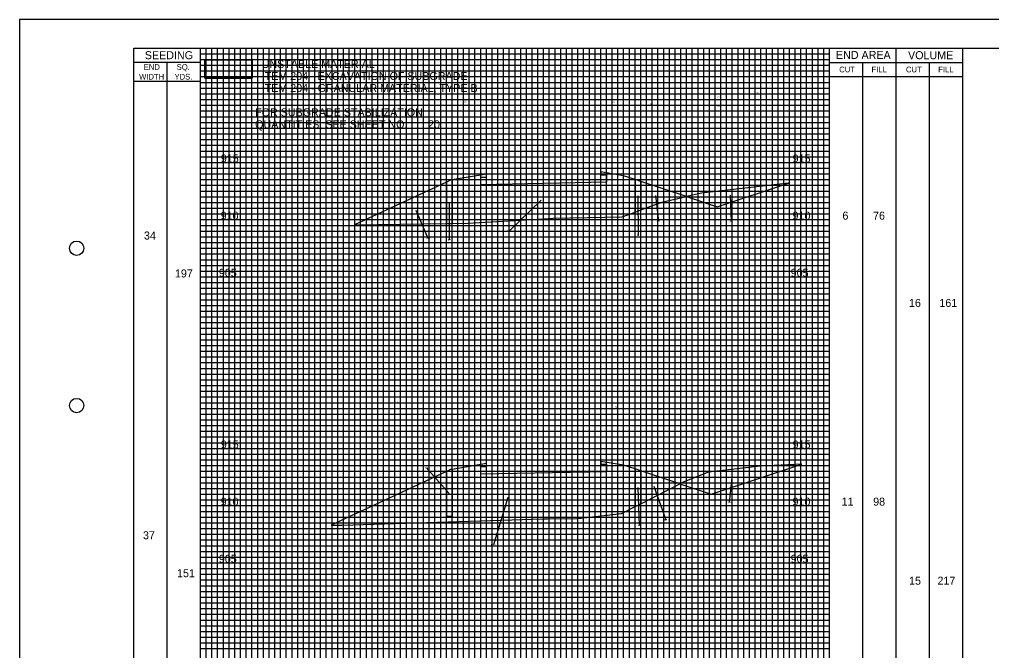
# Model space of a CAD drawing. Extents: x -73 to 160, y -2 to 1877.
# Drawn here: x -10 to 75, y 627.3 to 682.5 of the extents above; entities that cross this region are included whole.
import ezdxf

# ---------------------------------------------------------------- set-up
doc = ezdxf.new("R2010")
doc.units = 0
for name, color, linetype in [('DR_P_Flood_Boundary', 7, 'Continuous'), ('GK_Cells', 7, 'Continuous'), ('PV_P_EOP', 7, 'Continuous'), ('RD_X_Fence', 7, 'Continuous'), ('TX_X_5', 7, 'Continuous'), ('UT_P_Water_Cells', 7, 'Continuous'), ('XS_P_Pavt_Surface', 7, 'Continuous'), ('XS_P_Special_Benching', 7, 'Continuous'), ('XS_X_Ground_Line', 7, 'Continuous')]:
    doc.layers.add(name, color=color, linetype=linetype)

msp = doc.modelspace()

# ---------------------------------------------------------------- linework, layer by layer
at = {"layer": 'DR_P_Flood_Boundary'}
for p, q in [((10.832, 575), (10.832, 680)), ((15.832, 575), (15.832, 680)), ((20.832, 575), (20.832, 680)), ((25.832, 575), (25.832, 680)), ((30.832, 575), (30.832, 680)), ((35.832, 575), (35.832, 680)), ((40.832, 575), (40.832, 680)), ((45.832, 575), (45.832, 680)), ((50.832, 575), (50.832, 680)), ((55.832, 575), (55.832, 680)), ((5.832, 675), (60.832, 675)), ((5.832, 670), (60.832, 670)), ((5.832, 665), (60.832, 665)), ((5.832, 660), (60.832, 660)), ((5.832, 655), (60.832, 655)), ((5.832, 650), (60.832, 650)), ((5.832, 645), (60.832, 645)), ((5.832, 640), (60.832, 640)), ((5.832, 635), (60.832, 635)), ((5.832, 630), (60.832, 630))]:
    msp.add_line(p, q, dxfattribs=at)
at = {"layer": 'GK_Cells'}
msp.add_lwpolyline([(0, 680), (157.5, 680), (157.5, 575), (0, 575)], close=True, dxfattribs=at)
for centre in [(-5, 662.5), (-5, 648.75)]:
    msp.add_circle(centre, 0.625, dxfattribs=at)
at = {"layer": 'PV_P_EOP'}
msp.add_lwpolyline([(6.212, 678.971), (10.353, 678.971), (10.353, 677.356), (6.212, 677.356)], close=True, dxfattribs=at)
msp.add_lwpolyline([(6.212, 677.356), (10.353, 677.356), (10.353, 678.971), (6.212, 678.971), (6.212, 677.356)], dxfattribs=at)
at = {"layer": 'RD_X_Fence'}
for p, q in [((30.832, 668.97), (27.832, 668.47)), ((42.832, 668.837), (40.832, 669.17)), ((27.332, 668.278), (19.296, 664.541)), ((27.698, 668.448), (27.332, 668.278)), ((27.332, 664.661), (27.332, 668.278)), ((27.332, 668.278), (27.332, 664.661)), ((27.832, 668.47), (27.698, 668.448)), ((27.832, 664.668), (27.832, 668.47)), ((27.832, 668.47), (27.832, 664.668)), ((30.332, 668.71), (30.832, 668.72)), ((30.332, 668.043), (30.332, 668.71)), ((41.332, 668.263), (30.332, 668.043)), ((40.832, 668.92), (41.332, 668.93)), ((41.332, 668.93), (41.332, 668.263)), ((43.832, 668.503), (42.832, 668.837)), ((43.832, 665.663), (43.832, 668.503)), ((44.332, 668.337), (43.832, 668.503)), ((43.832, 668.503), (43.832, 665.663)), ((44.332, 665.848), (44.332, 668.337)), ((44.332, 668.337), (44.332, 665.848)), ((48.314, 667.009), (44.332, 668.337)), ((51.012, 666.11), (57.249, 668.189)), ((27.585, 666.527), (27.581, 663.246)), ((35.63, 666.701), (32.819, 663.985)), ((44.077, 667.088), (44.105, 663.627)), ((45.623, 667.101), (45.867, 664.866)), ((48.314, 667.009), (51.012, 666.11)), ((52.151, 667.139), (52.23, 664.836)), ((24.654, 665.826), (25.723, 663.389)), ((43.832, 665.663), (44.332, 665.848)), ((19.296, 664.541), (27.332, 664.661)), ((27.332, 664.661), (27.832, 664.668)), ((30.832, 643.67), (27.832, 643.17)), ((42.832, 643.537), (40.832, 643.87)), ((40.832, 643.62), (41.332, 643.63)), ((41.332, 643.63), (41.332, 642.963)), ((43.832, 643.203), (42.832, 643.537)), ((50.472, 640.99), (58.419, 643.639)), ((27.332, 642.978), (17.247, 638.288)), ((27.585, 641.068), (25.603, 643.3)), ((27.698, 643.148), (27.332, 642.978)), ((27.332, 639.047), (27.332, 642.978)), ((27.332, 642.978), (27.332, 639.047)), ((27.832, 643.17), (27.698, 643.148)), ((27.832, 643.17), (27.832, 639.047)), ((27.832, 639.047), (27.832, 643.17)), ((30.332, 643.41), (30.832, 643.42)), ((30.332, 642.743), (30.332, 643.41)), ((41.332, 642.963), (30.332, 642.743)), ((43.832, 639.918), (43.832, 643.203)), ((44.332, 643.037), (43.832, 643.203)), ((43.832, 643.203), (43.832, 639.918)), ((44.332, 640.171), (44.332, 643.037)), ((47.748, 641.898), (44.332, 643.037)), ((44.332, 643.037), (44.332, 640.171)), ((44.332, 640.171), (47.748, 641.898)), ((47.748, 641.898), (50.472, 640.99)), ((52.294, 642.431), (52.053, 640.31)), ((44.077, 641.582), (44.195, 638.249)), ((45.471, 641.702), (46.508, 638.756)), ((32.699, 640.717), (31.445, 636.582)), ((43.832, 639.918), (44.332, 640.171)), ((27.832, 639.047), (27.332, 639.047)), ((27.332, 639.047), (27.832, 639.047))]:
    msp.add_line(p, q, dxfattribs=at)
for points in [[(30.832, 668.72), (30.832, 668.866), (30.832, 668.97)], [(40.832, 669.17), (40.832, 669.066), (40.832, 668.92)], [(57.249, 668.189), (49.639, 667.308), (48.314, 667.009)], [(44.332, 665.848), (46.162, 666.524), (48.314, 667.009)], [(27.832, 664.668), (29.207, 664.688), (35.832, 665.072), (36.63, 665.118), (42.69, 665.241), (43.832, 665.663)], [(30.832, 643.42), (30.832, 643.566), (30.832, 643.67)], [(40.832, 643.87), (40.832, 643.766), (40.832, 643.62)], [(58.419, 643.639), (54.771, 643.464), (50.243, 642.938), (48.035, 642.043), (47.748, 641.898)], [(17.247, 638.288), (18.217, 638.303), (35.833, 638.835), (36.166, 638.845), (38.844, 638.879), (42.655, 639.322), (43.832, 639.918)]]:
    msp.add_lwpolyline(points, dxfattribs=at)
at = {"layer": 'TX_X_5'}
msp.add_lwpolyline([(-10, 572.5), (160, 572.5), (160, 682.5), (-10, 682.5)], close=True, dxfattribs=at)
at = {"layer": 'UT_P_Water_Cells'}
for p, q in [((6.332, 575), (6.332, 680)), ((6.832, 575), (6.832, 680)), ((7.332, 575), (7.332, 680)), ((7.832, 575), (7.832, 680)), ((8.332, 575), (8.332, 680)), ((8.832, 575), (8.832, 680)), ((9.332, 575), (9.332, 680)), ((9.832, 575), (9.832, 680)), ((10.332, 575), (10.332, 680)), ((11.332, 575), (11.332, 680)), ((11.832, 575), (11.832, 680)), ((12.332, 575), (12.332, 680)), ((12.832, 575), (12.832, 680)), ((13.332, 575), (13.332, 680)), ((13.832, 575), (13.832, 680)), ((14.332, 575), (14.332, 680)), ((14.832, 575), (14.832, 680)), ((15.332, 575), (15.332, 680)), ((16.332, 575), (16.332, 680)), ((16.832, 575), (16.832, 680)), ((17.332, 575), (17.332, 680)), ((17.832, 575), (17.832, 680)), ((18.332, 575), (18.332, 680)), ((18.832, 575), (18.832, 680)), ((19.332, 575), (19.332, 680)), ((19.832, 575), (19.832, 680)), ((20.332, 575), (20.332, 680)), ((21.332, 575), (21.332, 680)), ((21.832, 575), (21.832, 680)), ((22.332, 575), (22.332, 680)), ((22.832, 575), (22.832, 680)), ((23.332, 575), (23.332, 680)), ((23.832, 575), (23.832, 680)), ((24.332, 575), (24.332, 680)), ((24.832, 575), (24.832, 680)), ((25.332, 575), (25.332, 680)), ((26.332, 575), (26.332, 680)), ((26.832, 575), (26.832, 680)), ((27.332, 575), (27.332, 680)), ((27.832, 575), (27.832, 680)), ((28.332, 575), (28.332, 680)), ((28.832, 575), (28.832, 680)), ((29.332, 575), (29.332, 680)), ((29.832, 575), (29.832, 680)), ((30.332, 575), (30.332, 680)), ((31.332, 575), (31.332, 680)), ((31.832, 575), (31.832, 680)), ((32.332, 575), (32.332, 680)), ((32.832, 575), (32.832, 680)), ((33.332, 575), (33.332, 680)), ((33.832, 575), (33.832, 680)), ((34.332, 575), (34.332, 680)), ((34.832, 575), (34.832, 680)), ((35.332, 575), (35.332, 680)), ((36.332, 575), (36.332, 680)), ((36.832, 575), (36.832, 680)), ((37.332, 575), (37.332, 680)), ((37.832, 575), (37.832, 680)), ((38.332, 575), (38.332, 680)), ((38.832, 575), (38.832, 680)), ((39.332, 575), (39.332, 680)), ((39.832, 575), (39.832, 680)), ((40.332, 575), (40.332, 680)), ((41.332, 575), (41.332, 680)), ((41.832, 575), (41.832, 680)), ((42.332, 575), (42.332, 680)), ((42.832, 575), (42.832, 680)), ((43.332, 575), (43.332, 680)), ((43.832, 575), (43.832, 680)), ((44.332, 575), (44.332, 680)), ((44.832, 575), (44.832, 680)), ((45.332, 575), (45.332, 680)), ((46.332, 575), (46.332, 680)), ((46.832, 575), (46.832, 680)), ((47.332, 575), (47.332, 680)), ((47.832, 575), (47.832, 680)), ((48.332, 575), (48.332, 680)), ((48.832, 575), (48.832, 680)), ((49.332, 575), (49.332, 680)), ((49.832, 575), (49.832, 680)), ((50.332, 575), (50.332, 680)), ((51.332, 575), (51.332, 680)), ((51.832, 575), (51.832, 680)), ((52.332, 575), (52.332, 680)), ((52.832, 575), (52.832, 680)), ((53.332, 575), (53.332, 680)), ((53.832, 575), (53.832, 680)), ((54.332, 575), (54.332, 680)), ((54.832, 575), (54.832, 680)), ((55.332, 575), (55.332, 680)), ((56.332, 575), (56.332, 680)), ((56.832, 575), (56.832, 680)), ((57.332, 575), (57.332, 680)), ((57.832, 575), (57.832, 680)), ((58.332, 575), (58.332, 680)), ((58.832, 575), (58.832, 680)), ((59.332, 575), (59.332, 680)), ((59.832, 575), (59.832, 680)), ((60.332, 575), (60.332, 680)), ((5.832, 679.5), (60.832, 679.5)), ((5.832, 679), (60.832, 679)), ((5.832, 678.5), (60.832, 678.5)), ((5.832, 678), (60.832, 678)), ((5.832, 677.5), (60.832, 677.5)), ((5.832, 677), (60.832, 677)), ((5.832, 676.5), (60.832, 676.5)), ((5.832, 676), (60.832, 676)), ((5.832, 675.5), (60.832, 675.5)), ((5.832, 674.5), (60.832, 674.5)), ((5.832, 674), (60.832, 674)), ((5.832, 673.5), (60.832, 673.5)), ((5.832, 673), (60.832, 673)), ((5.832, 672.5), (60.832, 672.5)), ((5.832, 672), (60.832, 672)), ((5.832, 671.5), (60.832, 671.5)), ((5.832, 671), (60.832, 671)), ((5.832, 670.5), (60.832, 670.5)), ((5.832, 669.5), (60.832, 669.5)), ((5.832, 669), (60.832, 669)), ((5.832, 668.5), (60.832, 668.5)), ((5.832, 668), (60.832, 668)), ((5.832, 667.5), (60.832, 667.5)), ((5.832, 667), (60.832, 667)), ((5.832, 666.5), (60.832, 666.5)), ((5.832, 666), (60.832, 666)), ((5.832, 665.5), (60.832, 665.5)), ((5.832, 664.5), (60.832, 664.5)), ((5.832, 664), (60.832, 664)), ((5.832, 663.5), (60.832, 663.5)), ((5.832, 663), (60.832, 663)), ((5.832, 662.5), (60.832, 662.5)), ((5.832, 662), (60.832, 662)), ((5.832, 661.5), (60.832, 661.5)), ((5.832, 661), (60.832, 661)), ((5.832, 660.5), (60.832, 660.5)), ((5.832, 659.5), (60.832, 659.5)), ((5.832, 659), (60.832, 659)), ((5.832, 658.5), (60.832, 658.5)), ((5.832, 658), (60.832, 658)), ((5.832, 657.5), (60.832, 657.5)), ((5.832, 657), (60.832, 657)), ((5.832, 656.5), (60.832, 656.5)), ((5.832, 656), (60.832, 656)), ((5.832, 655.5), (60.832, 655.5)), ((5.832, 654.5), (60.832, 654.5)), ((5.832, 654), (60.832, 654)), ((5.832, 653.5), (60.832, 653.5)), ((5.832, 653), (60.832, 653)), ((5.832, 652.5), (60.832, 652.5)), ((5.832, 652), (60.832, 652)), ((5.832, 651.5), (60.832, 651.5)), ((5.832, 651), (60.832, 651)), ((5.832, 650.5), (60.832, 650.5)), ((5.832, 649.5), (60.832, 649.5)), ((5.832, 649), (60.832, 649)), ((5.832, 648.5), (60.832, 648.5)), ((5.832, 648), (60.832, 648)), ((5.832, 647.5), (60.832, 647.5)), ((5.832, 647), (60.832, 647)), ((5.832, 646.5), (60.832, 646.5)), ((5.832, 646), (60.832, 646)), ((5.832, 645.5), (60.832, 645.5)), ((5.832, 644.5), (60.832, 644.5)), ((5.832, 644), (60.832, 644)), ((5.832, 643.5), (60.832, 643.5)), ((5.832, 643), (60.832, 643)), ((5.832, 642.5), (60.832, 642.5)), ((5.832, 642), (60.832, 642)), ((5.832, 641.5), (60.832, 641.5)), ((5.832, 641), (60.832, 641)), ((5.832, 640.5), (60.832, 640.5)), ((5.832, 639.5), (60.832, 639.5)), ((5.832, 639), (60.832, 639)), ((5.832, 638.5), (60.832, 638.5)), ((5.832, 638), (60.832, 638)), ((5.832, 637.5), (60.832, 637.5)), ((5.832, 637), (60.832, 637)), ((5.832, 636.5), (60.832, 636.5)), ((5.832, 636), (60.832, 636)), ((5.832, 635.5), (60.832, 635.5)), ((5.832, 634.5), (60.832, 634.5)), ((5.832, 634), (60.832, 634)), ((5.832, 633.5), (60.832, 633.5)), ((5.832, 633), (60.832, 633)), ((5.832, 632.5), (60.832, 632.5)), ((5.832, 632), (60.832, 632)), ((5.832, 631.5), (60.832, 631.5)), ((5.832, 631), (60.832, 631)), ((5.832, 630.5), (60.832, 630.5)), ((5.832, 629.5), (60.832, 629.5)), ((5.832, 629), (60.832, 629)), ((5.832, 628.5), (60.832, 628.5)), ((5.832, 628), (60.832, 628)), ((5.832, 627.5), (60.832, 627.5))]:
    msp.add_line(p, q, dxfattribs=at)
at = {"layer": 'XS_X_Ground_Line'}
for p, q in [((5.832, 575), (5.832, 680)), ((60.832, 575), (60.832, 680)), ((66.667, 575), (66.667, 680)), ((72.5, 575), (72.5, 680)), ((5.832, 678.75), (0, 678.75)), ((2.916, 575), (2.916, 678.75)), ((60.832, 678.75), (72.5, 678.75)), ((63.75, 575), (63.75, 678.75)), ((69.583, 575), (69.583, 678.75)), ((60.832, 677.5), (72.5, 677.5)), ((5.832, 677.083), (0, 677.083))]:
    msp.add_line(p, q, dxfattribs=at)

# ---------------------------------------------------------------- texts
at = {"layer": 'RD_X_Fence'}
for s, p in [('2.5', (51.017, 675.65)), ('6.0', (54.379, 675.989)), ('9.3', (25.433, 675.366)), ('3.2', (28.811, 675.265)), ('2.0', (41.752, 675.189)), ('8.6', (44.993, 675.037)), ('6.7', (51.01, 674.885)), ('4.7', (45.721, 664.796)), ('6.2', (52.083, 664.766)), ('53.3', (32.611, 663.915)), ('14.5', (25.544, 663.319)), ('1.9', (27.462, 663.176)), ('1.3', (43.987, 663.557)), ('11.6', (22.76, 648.971)), ('3.2', (29.122, 648.844)), ('2.0', (42.05, 648.559)), ('8.1', (45.86, 648.37)), ('8.4', (50.436, 648.401)), ('2.0', (25.452, 643.23)), ('11.2', (51.902, 640.24)), ('4.9', (46.361, 638.686)), ('1.5', (44.076, 638.179)), ('89.0', (31.231, 636.512))]:
    msp.add_text(s, height=0.14, dxfattribs=at).set_placement(p)
at = {"layer": 'XS_P_Pavt_Surface'}
for s, p in [('915', (7.609, 670)), ('915', (57.609, 670)), ('910', (7.598, 665)), ('910', (57.598, 665)), ('6', (61.961, 665)), ('76', (64.639, 665)), ('34', (0.888, 663.262)), ('197', (3.597, 659.946)), ('905', (7.438, 660)), ('905', (57.438, 660)), ('16', (67.779, 657.37)), ('161', (70.438, 657.37)), ('915', (7.609, 645)), ('915', (57.609, 645)), ('910', (7.598, 640)), ('910', (57.598, 640)), ('11', (61.892, 640)), ('98', (64.648, 640)), ('37', (0.803, 637.061)), ('905', (7.438, 635)), ('905', (57.438, 635)), ('151', (3.781, 633.744)), ('15', (67.787, 633.088)), ('217', (70.27, 633.088))]:
    msp.add_text(s, height=0.7, dxfattribs=at).set_placement(p)
at = {"layer": 'XS_P_Special_Benching'}
for s, p in [('UNSTABLE MATERIAL', (11.181, 678.257)), ('ITEM 204 - EXCAVATION OF SUBGRADE', (11.181, 677.207)), ('ITEM 204 - GRANULAR MATERIAL, TYPE B', (11.181, 676.157)), ('FOR SUBGRADE STABILIZATION', (10.609, 674.03)), ('QUANTITIES, SEE SHEET NO.', (10.609, 672.98)), ('20', (25.727, 672.98))]:
    msp.add_text(s, height=0.7, dxfattribs=at).set_placement(p)
at = {"layer": 'XS_X_Ground_Line'}
for s, height, p in [('SEEDING', 0.7, (0.964, 679.025)), ('END AREA', 0.7, (61.394, 679.047)), ('VOLUME', 0.7, (67.698, 679.025)), ('END', 0.5, (0.87, 678.092)), ('SQ.', 0.5, (3.748, 678.092)), ('CUT', 0.5, (61.683, 677.875)), ('FILL', 0.5, (64.502, 677.875)), ('CUT', 0.5, (67.517, 677.875)), ('FILL', 0.5, (70.335, 677.875)), ('WIDTH', 0.5, (0.462, 677.242)), ('YDS.', 0.5, (3.563, 677.242))]:
    msp.add_text(s, height=height, dxfattribs=at).set_placement(p)

doc.saveas('drawing.dxf')
